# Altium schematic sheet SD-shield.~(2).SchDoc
size A; SheetNumber: 1; SheetTotal: 1
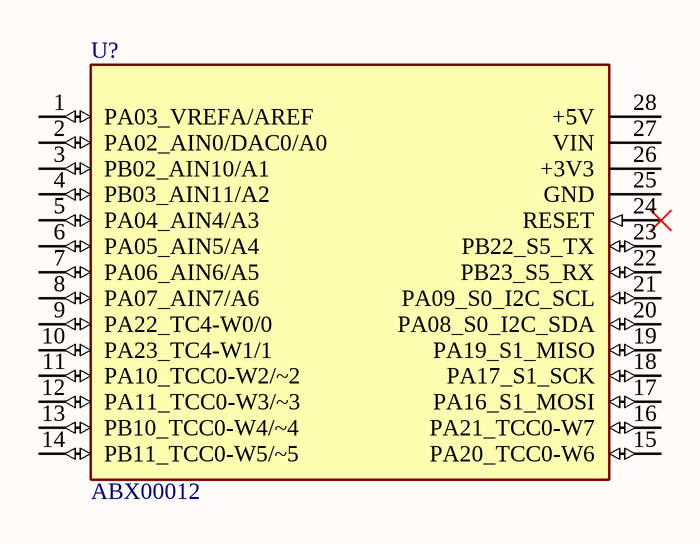
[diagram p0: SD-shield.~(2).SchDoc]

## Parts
U?  ABX00012  [ARDUINO_ABX00012]

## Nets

Not connected (* = marked no-connect by the designer): U? 1(PA03_VREFA/AREF) 2(PA02_AIN0/DAC0/A0) 3(PB02_AIN10/A1) 4(PB03_AIN11/A2) 5(PA04_AIN4/A3) 6(PA05_AIN5/A4) 7(PA06_AIN6/A5) 8(PA07_AIN7/A6) 9(PA22_TC4-W0/0) 10(PA23_TC4-W1/1) 11(PA10_TCC0-W2/~2) 12(PA11_TCC0-W3/~3) 13(PB10_TCC0-W4/~4) 14(PB11_TCC0-W5/~5) 15(PA20_TCC0-W6) 16(PA21_TCC0-W7) 17(PA16_S1_MOSI) 18(PA17_S1_SCK) 19(PA19_S1_MISO) 20(PA08_S0_I2C_SDA) 21(PA09_S0_I2C_SCL) 22(PB23_S5_RX) 23(PB22_S5_TX) 24(RESET)* 25(GND) 26(+3V3) 27(VIN) 28(+5V)

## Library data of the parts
U? = ABX00012: Mkrzero Brd With Headers Mounted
